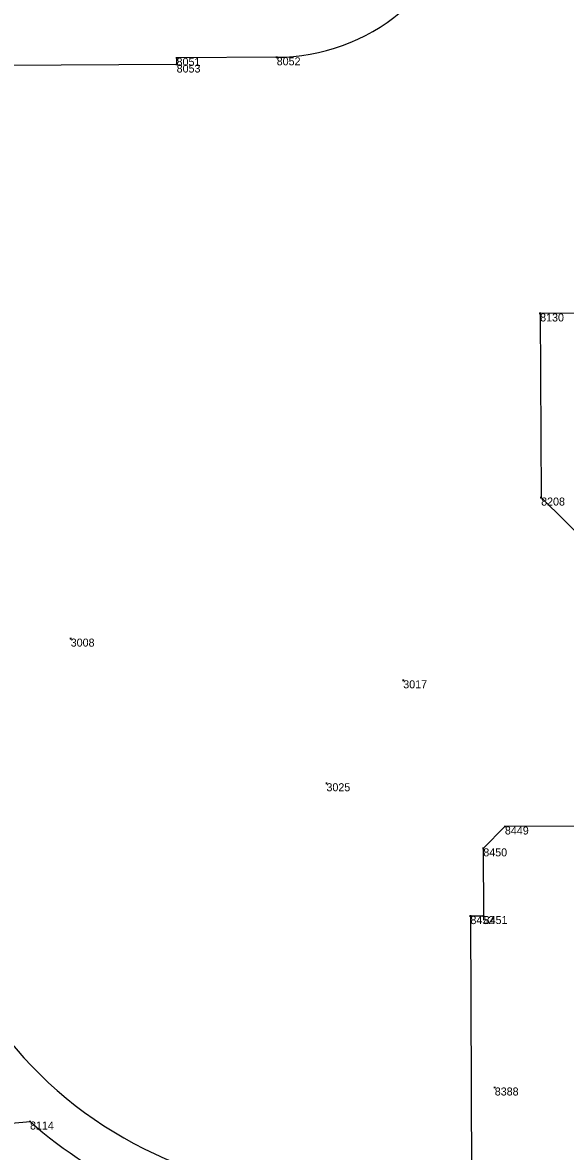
# Model space of a CAD drawing. Extents: x 2145146 to 2158053, y 137507 to 150829.
# Drawn here: x 2151520 to 2152334, y 143925 to 145617 of the extents above; entities that cross this region are included whole.
import ezdxf

# ---------------------------------------------------------------- set-up
doc = ezdxf.new("R2010")
doc.units = 0
for name, color, linetype in [('ALIGN_Cogo Points', 7, 'Continuous'), ('ALIGN_ROW Line', 7, 'Continuous'), ('PLSS_Property Line', 7, 'Continuous')]:
    doc.layers.add(name, color=color, linetype=linetype)

msp = doc.modelspace()

# ---------------------------------------------------------------- linework, layer by layer
at = {"layer": 'ALIGN_Cogo Points'}
for points in [[(2151751.2, 145563.8), (2151751.2, 145565), (2151751.2, 145563.8), (2151750, 145563.8), (2151751.2, 145563.8), (2151751.2, 145562.6), (2151751.2, 145563.8), (2151752.4, 145563.8)], [(2151751.3, 145553.8), (2151751.3, 145555), (2151751.3, 145553.8), (2151750.1, 145553.8), (2151751.3, 145553.8), (2151751.3, 145552.6), (2151751.3, 145553.8), (2151752.5, 145553.8)], [(2151901.3, 145564.6), (2151901.3, 145565.8), (2151901.3, 145564.6), (2151900.1, 145564.6), (2151901.3, 145564.6), (2151901.3, 145563.4), (2151901.3, 145564.6), (2151902.5, 145564.6)], [(2152296.2, 145180.7), (2152296.2, 145181.9), (2152296.2, 145180.7), (2152295, 145180.7), (2152296.2, 145180.7), (2152296.2, 145179.5), (2152296.2, 145180.7), (2152297.4, 145180.7)], [(2152297.7, 144904.8), (2152297.7, 144906), (2152297.7, 144904.8), (2152296.5, 144904.8), (2152297.7, 144904.8), (2152297.7, 144903.6), (2152297.7, 144904.8), (2152298.9, 144904.8)], [(2151592.5, 144693.4), (2151592.5, 144694.6), (2151592.5, 144693.4), (2151591.3, 144693.4), (2151592.5, 144693.4), (2151592.5, 144692.2), (2151592.5, 144693.4), (2151593.7, 144693.4)], [(2152091, 144630.9), (2152091, 144632.1), (2152091, 144630.9), (2152089.8, 144630.9), (2152091, 144630.9), (2152091, 144629.7), (2152091, 144630.9), (2152092.2, 144630.9)], [(2151975.9, 144476.6), (2151975.9, 144477.8), (2151975.9, 144476.6), (2151974.7, 144476.6), (2151975.9, 144476.6), (2151975.9, 144475.4), (2151975.9, 144476.6), (2151977.1, 144476.6)], [(2152243.4, 144411.8), (2152243.4, 144413), (2152243.4, 144411.8), (2152242.2, 144411.8), (2152243.4, 144411.8), (2152243.4, 144410.6), (2152243.4, 144411.8), (2152244.6, 144411.8)], [(2152211, 144379), (2152211, 144380.2), (2152211, 144379), (2152209.8, 144379), (2152211, 144379), (2152211, 144377.8), (2152211, 144379), (2152212.2, 144379)], [(2152191.7, 144277.5), (2152191.7, 144278.7), (2152191.7, 144277.5), (2152190.5, 144277.5), (2152191.7, 144277.5), (2152191.7, 144276.3), (2152191.7, 144277.5), (2152192.9, 144277.5)], [(2152211.5, 144277.6), (2152211.5, 144278.8), (2152211.5, 144277.6), (2152210.3, 144277.6), (2152211.5, 144277.6), (2152211.5, 144276.4), (2152211.5, 144277.6), (2152212.7, 144277.6)], [(2152228.2, 144020.6), (2152228.2, 144021.8), (2152228.2, 144020.6), (2152227, 144020.6), (2152228.2, 144020.6), (2152228.2, 144019.4), (2152228.2, 144020.6), (2152229.4, 144020.6)], [(2151531.5, 143969.6), (2151531.5, 143970.8), (2151531.5, 143969.6), (2151530.3, 143969.6), (2151531.5, 143969.6), (2151531.5, 143968.4), (2151531.5, 143969.6), (2151532.7, 143969.6)]]:
    msp.add_lwpolyline(points, dxfattribs=at)
at = {"layer": 'ALIGN_ROW Line'}
msp.add_lwpolyline([(2151901.3, 145564.6), (2151901.3, 145564.6), (2151751.2, 145563.8), (2151751.3, 145553.8), (2151318.9, 145551.3)], dxfattribs=at)
msp.add_arc((2151899.6, 145857.5), 292.9, 270.3251, 309.7426, dxfattribs=at)
at = {"layer": 'PLSS_Property Line'}
for points in [[(2152870.9, 145699), (2152870.9, 145699), (2152531.6, 145796.4), (2152448.8, 145508), (2152450.5, 145181.5), (2152296.2, 145180.7), (2152297.7, 144904.8), (2152369, 144834.2), (2152763.9, 144836.2), (2152765.8, 144468.4), (2152790.9, 144443.5), (2152791.4, 144359.7), (2152585.3, 144358.6), (2152560.2, 144383.4), (2152560, 144413.4), (2152243.4, 144411.8), (2152211, 144379), (2152211.5, 144277.6), (2152191.7, 144277.5), (2152193.9, 143760.5), (2152292.1, 143739.4), (2152358.2, 143726.6)], [(2151475.4, 143964.6), (2151475.4, 143964.6), (2151531.5, 143969.6)]]:
    msp.add_lwpolyline(points, dxfattribs=at)
for radius, start, end in [(612.3, 210.5623, 263.3737), (674.3, 228.7686, 246.0665)]:
    msp.add_arc((2151975.9, 144476.6), radius, start, end, dxfattribs=at)

# ---------------------------------------------------------------- texts
at = {"layer": 'ALIGN_Cogo Points'}
for s, p in [('8051', (2151751.2, 145551.8)), ('8053', (2151751.3, 145541.8)), ('8052', (2151901.3, 145552.6)), ('8130', (2152296.2, 145168.7)), ('8208', (2152297.7, 144892.8)), ('3008', (2151592.5, 144681.4)), ('3017', (2152091, 144618.9)), ('3025', (2151975.9, 144464.6)), ('8449', (2152243.4, 144399.8)), ('8450', (2152211, 144367)), ('8452', (2152191.7, 144265.5)), ('8451', (2152211.5, 144265.6)), ('8388', (2152228.2, 144008.6)), ('8114', (2151531.5, 143957.6))]:
    msp.add_text(s, height=12, dxfattribs=at).set_placement(p)

doc.saveas('drawing.dxf')
